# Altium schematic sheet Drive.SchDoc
size 177 x 101 mm; SheetNumber: 1; SheetTotal: 1
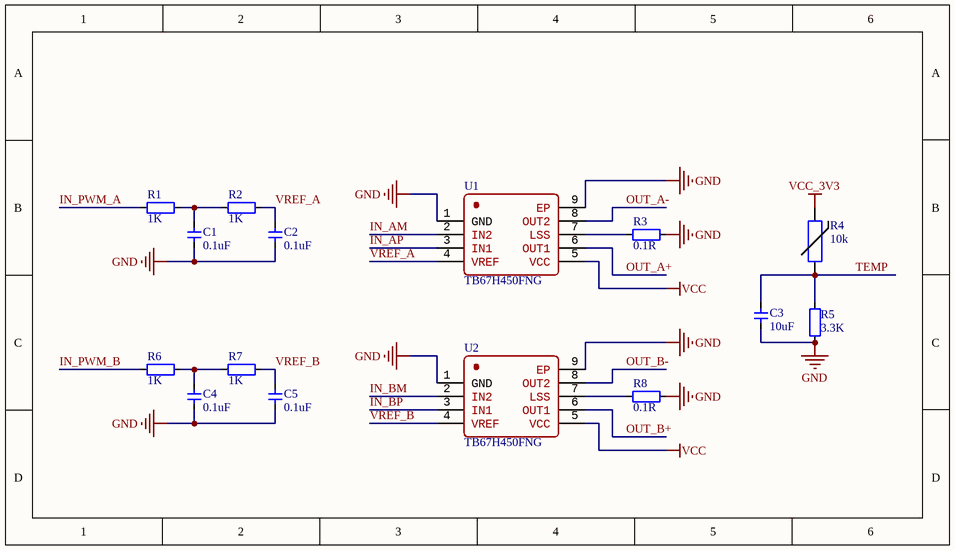
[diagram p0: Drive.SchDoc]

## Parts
C1  0.1uF  [CAP_0402]
C2  0.1uF  [CAP_0402]
C3  10uF  [CAP_0402]
C4  0.1uF  [CAP_0402]
C5  0.1uF  [CAP_0402]
R1  1K  [RES_0402]
R2  1K  [RES_0402]
R3  0.1R  [1206-RES]
R4  value 10k  [RES_0402]  (hidden comment: NCP15XH103F03RC)
R5  3.3K  [RES_0402]
R6  1K  [RES_0402]
R7  1K  [RES_0402]
R8  0.1R  [1206-RES]
U1  TB67H450FNG  [SO-8-PAD]
U2  TB67H450FNG  [SO-8-PAD]

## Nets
GND: C1.1 C2.1 C3.1 C4.1 C5.1 R3.2 R5.1 R8.2 U1.1(GND) U1.9(EP) U2.1(GND) U2.9(EP)
VCC: U1.5(VCC) U2.5(VCC)
VCC_3V3: R4.2
IN_AM: U1.2(IN2)
IN_AP: U1.3(IN1)
IN_BM: U2.2(IN2)
IN_BP: U2.3(IN1)
IN_PWM_A: R1.1
IN_PWM_B: R6.1
OUT_A+: U1.6(OUT1)
OUT_A-: U1.8(OUT2)
OUT_B+: U2.6(OUT1)
OUT_B-: U2.8(OUT2)
TEMP: C3.2 R4.1 R5.2
VREF_A: C2.2 R2.2 U1.4(VREF)
VREF_B: C5.2 R7.2 U2.4(VREF)
NetC1_2: C1.2 R1.2 R2.1
NetC4_2: C4.2 R6.2 R7.1
NetR3_1: R3.1 U1.7(LSS)
NetR8_1: R8.1 U2.7(LSS)

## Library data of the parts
C1-C5 = 电容-0402: Capacitor; Value: 0.1u
R1 R2 R5-R7 = 电阻-0402: Resistor; Value: 22R
R3 R8 = 电阻-1206: Resistor; Value: 22R
R4 = NCP15XH103F03RC: THERMISTOR 10K OHM NTC 0402 SMD
U1 U2 = TB67H450FNG: PWM Chopper Type DC Brushed Motor Driver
